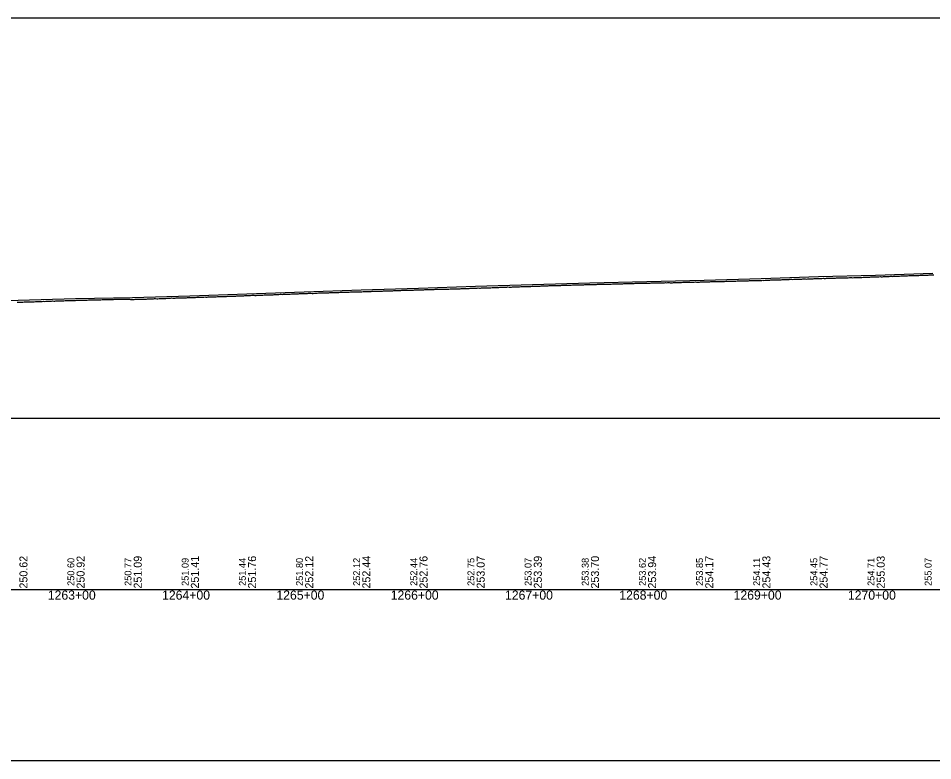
# Model space of a CAD drawing. Extents: x -3627 to 47473, y 2850 to 4350.
# Drawn here: x 13627 to 14427, y 2850 to 3500 of the extents above; entities that cross this region are included whole.
import ezdxf

# ---------------------------------------------------------------- set-up
doc = ezdxf.new("R2010")
doc.units = 0
for name, color, linetype in [('RD_DDB_Profile_EX', 7, 'Continuous'), ('RD_DDB_Profile_PR', 7, 'Continuous'), ('RD_DDB_StaTX', 7, 'Continuous'), ('RD_DDB_StripGrade', 7, 'Continuous'), ('RD_GPK_Profile_Cell', 7, 'Continuous'), ('RD_SHT_ShtClip', 7, 'Continuous')]:
    doc.layers.add(name, color=color, linetype=linetype)

msp = doc.modelspace()

# ---------------------------------------------------------------- linework, layer by layer
at = {"layer": 'RD_DDB_Profile_EX'}
for points in [[(14255.212154, 3269.888575), (14256.208332, 3270.01727), (14257.211431, 3270.0104), (14258.21036, 3270.0803), (14259.213447, 3270.05244), (14260.216534, 3270.00943), (14261.208566, 3270.016285), (14262.211652, 3270.17328), (14263.160721, 3270.16539), (14264.163914, 3270.21514), (14265.161646, 3270.215845), (14266.159104, 3270.228985), (14267.162291, 3270.285905), (14268.166428, 3270.364425), (14269.163874, 3270.370585), (14270.161626, 3270.364065), (14271.164806, 3270.28536), (14272.162253, 3270.37729), (14273.16639, 3270.355355), (14273.703458, 3270.44157), (14274.706852, 3270.505755), (14275.703982, 3270.55652), (14276.70738, 3270.563455), (14277.699517, 3270.563345), (14278.702916, 3270.577575), (14279.699196, 3270.57086), (14280.703436, 3270.620755), (14281.706835, 3270.727745), (14282.703953, 3270.821175), (14283.707357, 3270.813755), (14284.703635, 3270.857195), (14285.707876, 3270.89277), (14286.699165, 3270.906795), (14287.703407, 3270.89949), (14288.699674, 3270.90017), (14289.703086, 3270.957025), (14290.700179, 3270.979085), (14291.703596, 3271.071755), (14292.70068, 3271.072425), (14293.704103, 3271.09341), (14294.700363, 3271.143805), (14295.699628, 3271.17185), (14296.697062, 3271.17933), (14297.701308, 3271.193385), (14298.697549, 3271.27973), (14299.700982, 3271.322465), (14300.698032, 3271.387115), (14301.70147, 3271.44393), (14302.705716, 3271.49385), (14303.701955, 3271.472125), (14304.705394, 3271.38602), (14305.697475, 3271.479), (14306.700915, 3271.59298), (14307.69795, 3271.58608), (14308.701396, 3271.644155), (14309.697624, 3271.60842), (14310.701872, 3271.64448), (14311.698096, 3271.724225), (14312.702344, 3271.731015), (14313.698563, 3271.75207), (14314.697063, 3271.794465), (14315.694072, 3271.83121), (14316.697531, 3271.687895), (14317.694529, 3271.75214), (14318.697995, 3271.972565), (14319.694203, 3271.895545), (14320.698454, 3271.88183), (14321.681263, 3271.94854), (14322.685493, 3271.99161), (14323.687805, 3272.179645), (14324.679811, 3272.18641), (14325.683237, 3272.243185), (14326.680346, 3272.279745), (14327.402521, 3272.2526), (14328.26452, 3272.253065), (14329.402779, 3272.25963), (14330.399444, 3272.323345), (14331.403032, 3272.34652), (14332.266746, 3272.302615), (14333.398667, 3272.309695), (14334.267858, 3272.39619), (14335.398909, 3272.339935), (14336.268971, 3272.33985), (14337.397973, 3272.50367), (14338.401567, 3272.503515), (14339.398209, 3272.46055), (14340.397196, 3272.47998), (14341.267273, 3272.479955), (14342.397432, 3272.58011), (14343.268392, 3272.623445), (14344.397663, 3272.667075), (14345.269511, 3272.623625), (14346.397886, 3272.667295), (14347.27063, 3272.66725), (14348.393511, 3272.7), (14349.265598, 3272.786835), (14350.392566, 3272.843485), (14351.39687, 3272.886945), (14352.400481, 3272.8), (14353.397083, 3272.79352), (14354.400701, 3272.930485)], [(14354.400701, 3272.930485), (14355.261866, 3272.973945), (14356.265958, 3273.0239), (14357.262979, 3272.89353), (14358.396527, 3272.912985), (14359.393098, 3273.06788), (14360.396728, 3273.06777), (14361.265205, 3273.11174), (14362.395787, 3273.14361), (14363.265402, 3273.143525), (14364.391393, 3273.130735), (14365.266521, 3273.04357), (14366.391582, 3273.26812), (14367.26764, 3273.31169), (14368.391764, 3273.211395), (14369.26876, 3273.211265), (14370.38737, 3273.44364), (14371.263698, 3273.44363), (14372.395324, 3273.45), (14373.264811, 3273.53735), (14374.395501, 3273.5873), (14375.265924, 3273.587445), (14376.394548, 3273.58742), (14377.326954, 3273.55), (14378.324748, 3273.50631), (14379.321977, 3273.675035), (14380.325404, 3273.637475), (14381.321637, 3273.819095), (14382.325835, 3273.781425), (14383.330033, 3273.756205), (14384.326485, 3273.8), (14385.329704, 3273.843855), (14386.321498, 3273.806155), (14387.325698, 3274.0315), (14388.321166, 3273.97562), (14389.325364, 3273.98168), (14390.322556, 3274.131895), (14391.325046, 3274.08791), (14392.304382, 3274.03183), (14393.301534, 3274.17007), (14394.297714, 3274.28229), (14395.301194, 3274.25852), (14396.298322, 3274.26488), (14397.295427, 3274.332655), (14398.297996, 3274.25), (14399.2951, 3274.39428), (14400.299306, 3274.44427), (14401.295479, 3274.49435), (14402.291867, 3274.477655), (14403.296074, 3274.516415), (14404.292244, 3274.48897), (14405.288624, 3274.522745), (14406.298278, 3274.7016), (14407.295307, 3274.712875), (14408.298661, 3274.75), (14409.295039, 3274.7), (14410.292043, 3274.7345), (14411.295419, 3274.90866), (14412.292411, 3274.879625), (14413.288768, 3274.79497), (14414.292166, 3274.77988), (14415.289133, 3274.920275), (14416.292735, 3274.995025), (14417.288902, 3274.99022), (14418.285844, 3274.964445), (14419.290052, 3275.00965), (14420.286393, 3275.08572), (14421.289835, 3275.12619), (14422.286753, 3275.2172), (14423.283085, 3275.17691), (14424.28655, 3275.317655), (14425.283442, 3275.345455), (14426.280309, 3275.32767), (14427.283254, 3275.37313), (14428.28012, 3275.3912)], [(13955.965101, 3261.59005), (13956.969299, 3261.63008), (13957.965531, 3261.67036), (13958.968505, 3261.68018), (13959.966314, 3261.740155), (13960.968944, 3261.78032), (13961.966742, 3261.79022), (13962.969729, 3261.819615), (13963.965969, 3261.85), (13965.034611, 3261.85972), (13966.031974, 3261.95), (13967.034589, 3261.901745), (13968.02579, 3261.90178), (13969.03006, 3261.98069), (13970.025761, 3262), (13971.03003, 3262.009585), (13972.033728, 3262.05), (13973.029433, 3262.1), (13974.033702, 3262.140505), (13975.029408, 3262.18117), (13976.02753, 3262.2), (13977.024852, 3262.19349), (13978.027509, 3262.234115), (13979.031777, 3262.302885), (13980.027487, 3262.331315), (13981.030157, 3262.27199), (13982.027466, 3262.353625), (13983.025592, 3262.421975), (13984.021307, 3262.431475), (13985.025575, 3262.45), (13986.028258, 3262.5), (13987.023986, 3262.59081), (13988.028252, 3262.6316), (13989.019404, 3262.613225), (13990.023671, 3262.613185), (13991.026366, 3262.65401), (13992.022099, 3262.72264), (13993.027387, 3262.70443), (13994.023112, 3262.73675), (13995.02124, 3262.77718), (13996.018513, 3262.836715), (13997.021235, 3262.79579), (13998.025501, 3262.78668), (13999.02123, 3262.77826), (14000.023965, 3262.828305), (14001.021224, 3262.9788), (14002.019357, 3262.9462), (14003.015091, 3262.937775), (14004.019356, 3262.928805), (14005.022103, 3263.011055), (14006.01785, 3263.07065), (14007.022113, 3263.13821), (14008.013225, 3263.179425), (14009.01749, 3263.161675), (14010.013228, 3263.153695), (14011.016, 3263.18), (14012.020263, 3263.22372), (14013.016014, 3263.21527), (14014.015125, 3263.206325), (14014.697908, 3263.33064), (14015.696146, 3263.305315), (14016.699021, 3263.305365), (14017.69725, 3263.38167), (14018.700134, 3263.42317), (14019.867069, 3263.49077), (14020.701247, 3263.49071), (14021.698268, 3263.54929), (14022.70236, 3263.657565), (14023.70056, 3263.691615), (14024.704654, 3263.649895), (14025.695783, 3263.716615), (14026.699878, 3263.733145), (14027.696877, 3263.73376), (14028.700972, 3263.74197), (14029.696812, 3263.86709), (14030.700905, 3263.82586), (14031.699073, 3263.8346), (14032.702009, 3263.892805), (14033.700167, 3263.985135), (14034.703112, 3263.99327), (14035.700126, 3264.00167), (14036.697136, 3264.04416), (14037.701229, 3264.086095), (14038.699362, 3264.07868), (14039.702333, 3264.128715), (14040.700456, 3264.129285), (14041.860354, 3264.16344), (14042.694504, 3264.205465), (14043.697481, 3264.21338), (14044.695597, 3264.203135), (14045.699692, 3264.406145), (14046.696691, 3264.39159), (14047.700786, 3264.406955), (14048.696702, 3264.492345), (14049.700795, 3264.473), (14050.697805, 3264.4814), (14051.701898, 3264.508405), (14052.699981, 3264.59404), (14053.703002, 3264.589475), (14054.700015, 3264.639885), (14055.703045, 3264.74742)], [(14055.703045, 3264.74742), (14056.701119, 3264.718085), (14057.699174, 3264.7188), (14058.702222, 3264.73359), (14059.700268, 3264.81223), (14060.69731, 3264.83181), (14061.694316, 3264.84731), (14062.69737, 3264.897345), (14063.69541, 3264.92006), (14064.873141, 3265.006855), (14065.877438, 3265.01358), (14066.867591, 3265.04182), (14067.871888, 3265.085), (14068.867382, 3265.142845), (14069.87168, 3265.142765), (14070.868422, 3265.12911), (14071.871471, 3265.10039), (14072.875769, 3265.20032), (14073.870512, 3265.236715), (14074.874808, 3265.272535), (14075.865712, 3265.2796), (14076.87001, 3265.336545), (14077.866734, 3265.415075), (14078.730553, 3265.372025), (14079.865775, 3265.41685), (14080.868853, 3265.580725), (14081.863621, 3265.581385), (14082.867916, 3265.538155), (14083.863427, 3265.53886), (14084.863099, 3265.644955), (14085.858602, 3265.659185), (14086.862898, 3265.638685), (14087.858866, 3265.7689), (14088.861974, 3265.80946), (14089.866269, 3265.802625), (14090.86178, 3265.853175), (14091.866075, 3265.9098), (14092.862751, 3265.95357), (14093.86052, 3265.959675), (14094.8572, 3265.94677), (14095.860326, 3266.02682), (14096.856994, 3266.03414), (14097.860133, 3266.040735), (14098.856789, 3266.071785), (14099.860386, 3266.12806), (14100.855892, 3266.185385), (14101.860188, 3266.191755), (14102.851032, 3266.267645), (14103.855329, 3266.267595), (14105.122149, 3266.26673), (14106.119181, 3266.261265), (14107.122665, 3266.31184), (14108.113503, 3266.336405), (14109.117736, 3266.39904), (14110.113709, 3266.39967), (14111.117942, 3266.45589), (14112.114946, 3266.493895), (14113.117414, 3266.5438), (14114.114416, 3266.55676), (14115.110386, 3266.563415), (14116.114619, 3266.651135), (14117.110589, 3266.595735), (14118.114822, 3266.56376), (14119.111077, 3266.664105), (14120.114322, 3266.708125), (14121.111277, 3266.77043), (14122.114533, 3266.726345), (14123.111477, 3266.832465), (14124.109551, 3266.82038), (14125.105801, 3266.82067), (14126.110035, 3266.86474), (14127.106001, 3266.892025), (14128.110235, 3266.9303), (14129.106201, 3266.99844), (14130.110435, 3267.004085), (14131.106401, 3266.87736), (14132.109967, 3266.99887), (14133.106869, 3267.03827), (14134.110175, 3267.088265), (14135.107066, 3267.09457), (14136.110383, 3267.10011), (14137.107263, 3267.150735), (14138.110852, 3267.206045), (14139.106824, 3267.195855), (14140.098447, 3267.195745), (14141.089175, 3267.19574), (14142.088211, 3267.22828), (14143.094654, 3267.166895), (14144.093097, 3267.17191), (14145.088996, 3267.30569), (14146.088092, 3267.338075), (14147.092336, 3267.38796), (14148.090497, 3267.40996), (14149.094741, 3267.448425), (14150.092893, 3267.49771), (14151.09646, 3267.591695), (14152.094594, 3267.584995), (14153.098835, 3267.5908), (14154.096961, 3267.59002), (14155.093863, 3267.596625), (14156.093001, 3267.59583)], [(14156.093001, 3267.59583), (14157.096239, 3267.68981), (14158.094673, 3267.72047), (14159.097895, 3267.70212), (14160.097036, 3267.663125), (14161.100243, 3267.768975), (14162.099389, 3267.71854), (14163.102582, 3267.730795), (14164.101734, 3267.72984), (14165.098702, 3267.905815), (14166.096071, 3267.910415), (14167.100311, 3267.96027), (14168.098406, 3267.948125), (14169.102646, 3267.954535), (14170.100732, 3268.054015), (14171.104972, 3268.0171), (14172.108117, 3268.06053), (14173.106511, 3268.05327), (14174.103546, 3268.010335), (14175.101623, 3268.08984), (14176.105862, 3268.11966), (14177.103932, 3268.082315), (14178.10817, 3268.09577), (14179.106232, 3268.188335), (14180.109666, 3268.23814), (14181.108865, 3268.251295), (14181.668883, 3268.251255), (14182.671988, 3268.301265), (14183.669912, 3268.294815), (14184.673027, 3268.26035), (14185.670941, 3268.34534), (14186.668054, 3268.380955), (14187.671195, 3268.394585), (14188.66813, 3268.395195), (14189.672234, 3268.45197), (14190.670332, 3268.39444), (14191.667256, 3268.431305), (14192.671361, 3268.524325), (14193.668286, 3268.55237), (14194.671441, 3268.509045), (14195.668543, 3268.60171), (14196.666459, 3268.53633), (14197.669582, 3268.5295), (14198.673686, 3268.497355), (14199.671593, 3268.51865), (14200.668706, 3268.65204), (14201.672811, 3268.645105), (14202.669736, 3268.672855), (14203.672866, 3268.73215), (14204.664717, 3268.739055), (14205.668823, 3268.788965), (14206.671954, 3268.788975), (14207.66888, 3268.796355), (14208.672984, 3268.83956), (14209.670097, 3268.838915), (14210.667023, 3268.90602), (14211.671127, 3268.89916), (14212.674267, 3268.939505), (14213.671204, 3268.96359), (14214.670206, 3269.00594), (14215.667122, 3268.97691), (14216.670273, 3268.93357), (14217.674378, 3268.996775), (14218.665266, 3269.096785), (14219.668416, 3269.120195), (14220.672521, 3269.076735), (14221.669448, 3269.077545), (14222.672607, 3269.07756), (14223.210142, 3269.097275), (14224.208818, 3269.18349), (14225.204956, 3269.184225), (14226.209167, 3269.22095), (14227.20704, 3269.256785), (14228.210176, 3269.28343), (14229.214384, 3269.246665), (14230.205261, 3269.296675), (14231.208396, 3269.34002), (14232.206248, 3269.382655), (14233.210456, 3269.425815), (14234.207427, 3269.426735), (14235.205286, 3269.432695), (14236.209494, 3269.44608), (14237.212617, 3269.43935), (14238.210459, 3269.468305), (14239.207711, 3269.53253), (14240.210833, 3269.6258), (14241.208672, 3269.618225), (14242.212878, 3269.63176), (14243.209048, 3269.675725), (14244.207717, 3269.67509), (14245.211924, 3269.681805), (14246.209763, 3269.71735), (14247.212862, 3269.724255), (14248.210136, 3269.74539), (14249.207973, 3269.78106), (14250.211071, 3269.824185), (14251.215276, 3269.860275), (14252.206182, 3269.903395), (14253.20928, 3269.960315), (14254.213484, 3269.88947), (14255.212154, 3269.888575)], [(13756.488564, 3254.767665), (13757.48749, 3254.84849), (13758.490472, 3254.972235), (13759.49464, 3255.022205), (13760.484665, 3255.03145), (13761.488833, 3255.11286), (13762.487777, 3255.08127), (13763.490741, 3255.034265), (13764.494909, 3255.093595), (13765.486389, 3255.17172), (13766.490559, 3255.190565), (13767.488064, 3255.2215), (13768.49101, 3255.20473), (13769.495179, 3255.204625), (13770.486679, 3255.32131), (13771.490849, 3255.30213), (13772.493787, 3255.342395), (13773.49128, 3255.39202), (13774.495448, 3255.382285), (13775.48697, 3255.4112), (13776.49114, 3255.42087), (13777.49406, 3255.46105), (13778.493064, 3255.61073), (13779.494454, 3255.61069), (13780.48726, 3255.542605), (13781.49143, 3255.612135), (13782.494333, 3255.6605), (13783.493354, 3255.780095), (13784.496244, 3255.690305), (13785.494227, 3255.721015), (13786.529588, 3255.78047), (13787.527622, 3255.801265), (13788.525637, 3255.8313), (13789.528522, 3255.83111), (13790.526531, 3255.992395), (13791.523262, 3255.972085), (13792.525932, 3255.98187), (13793.522667, 3256.04186), (13794.512479, 3256.022965), (13795.510494, 3256.023445), (13796.514649, 3256.0021), (13797.517941, 3256.083865), (13798.513263, 3256.146745), (13799.517417, 3256.14663), (13800.515395, 3256.22531), (13801.512142, 3256.303545), (13802.514884, 3256.335005), (13803.512844, 3256.34466), (13804.509587, 3256.4174), (13805.512347, 3256.376625), (13806.510288, 3256.48178), (13807.507028, 3256.48187), (13808.516539, 3256.39599), (13809.513092, 3256.52862), (13810.509833, 3256.641125), (13811.513988, 3256.632225), (13812.511881, 3256.67353), (13813.507277, 3256.72372), (13814.511433, 3256.74738), (13815.509307, 3256.706465), (13816.507161, 3256.767285), (13817.508872, 3256.85), (13818.506727, 3256.85859), (13819.50997, 3256.9), (13820.511735, 3257.02462), (13821.509567, 3256.991605), (13822.50738, 3257.02501), (13823.510448, 3257.116575), (13824.506991, 3257.13345), (13825.504784, 3257.15), (13826.507869, 3257.191765), (13827.505654, 3257.18366), (13828.502183, 3257.23382), (13829.505284, 3257.291885), (13830.508523, 3257.384055), (13831.506265, 3257.442095), (13832.508185, 3257.492085), (13833.369526, 3257.4683), (13834.368494, 3257.417945), (13835.371417, 3257.33398), (13836.369384, 3257.517545), (13837.373576, 3257.617505), (13838.372566, 3257.584305), (13839.374434, 3257.58422), (13840.373422, 3257.69169), (13841.371004, 3257.708245), (13842.368984, 3257.758345), (13843.371855, 3257.841655), (13844.370868, 3257.88314), (13845.37401, 3257.941545), (13846.373038, 3257.908545), (13847.375878, 3257.99146), (13848.320071, 3258.02408), (13849.322927, 3257.974095), (13850.321424, 3257.973835), (13851.324359, 3258.082505), (13852.316816, 3258.164965), (13853.319654, 3258.241245), (13854.323778, 3258.264945), (13855.321101, 3258.264535), (13856.323924, 3258.39114)], [(13856.323924, 3258.39114), (13857.322452, 3258.346325), (13858.325355, 3258.31411), (13859.322571, 3258.431915), (13860.326693, 3258.481895), (13861.325246, 3258.5), (13862.328123, 3258.53167), (13863.325335, 3258.485375), (13864.323475, 3258.48997), (13865.320796, 3258.542405), (13866.32356, 3258.740735), (13867.32214, 3258.762605), (13868.326264, 3258.771925), (13869.322198, 3258.781115), (13870.32632, 3258.783825), (13871.324926, 3258.79278), (13872.327748, 3258.852175), (13873.324955, 3258.922955), (13874.329077, 3258.99036), (13875.321786, 3259.00965), (13876.323178, 3258.982365), (13877.321811, 3259.02204), (13878.325935, 3259.10122), (13879.323148, 3259.07054), (13880.325931, 3259.170455), (13881.324589, 3259.23014), (13882.328712, 3259.33012), (13883.324558, 3259.35), (13884.32868, 3259.170065), (13885.327362, 3259.160115), (13886.330002, 3259.3), (13886.863725, 3259.33018), (13887.863355, 3259.32901), (13888.865904, 3259.408795), (13889.868971, 3259.55), (13890.866558, 3259.5), (13891.864491, 3259.539835), (13892.868735, 3259.589825), (13893.865146, 3259.6), (13894.864785, 3259.639785), (13895.867322, 3259.639795), (13896.863735, 3259.669505), (13897.867979, 3259.708415), (13898.865909, 3259.70785), (13899.870153, 3259.7795), (13900.866568, 3259.848965), (13901.864496, 3259.84865), (13902.86874, 3259.898595), (13903.86634, 3259.98978), (13904.85322, 3259.91815), (13905.852741, 3259.90719), (13906.847531, 3259.970505), (13907.851759, 3259.86921), (13908.851284, 3260.08794), (13909.847762, 3260.1397), (13910.850297, 3260.15), (13911.854525, 3260.15), (13912.854055, 3260.15), (13913.848836, 3260.139675), (13914.853064, 3260.189665), (13915.852598, 3260.26875), (13916.848601, 3260.268985), (13917.851603, 3260.418895), (13918.85583, 3260.368865), (13919.847143, 3260.37926), (13920.851372, 3260.37924), (13921.854369, 3260.41877), (13922.852189, 3260.43717), (13923.849915, 3260.516705), (13924.852908, 3260.6), (13925.855421, 3260.5), (13926.848457, 3260.58734), (13927.852686, 3260.62682), (13928.976973, 3260.687205), (13929.974891, 3260.72716), (13930.979086, 3260.8), (13931.975342, 3260.78966), (13932.973332, 3260.789565), (13933.971236, 3260.829245), (13934.975433, 3260.868835), (13935.971676, 3260.91907), (13936.974593, 3260.95), (13937.972479, 3260.96028), (13938.975042, 3261.05), (13939.972917, 3261.04895), (13940.975847, 3260.998805), (13941.972098, 3261.02888), (13942.976293, 3261.128805), (13943.972898, 3261.129105), (13944.970541, 3261.18885), (13945.968401, 3261.199345), (13946.972599, 3261.3), (13947.96759, 3261.249595), (13948.971786, 3261.27936), (13949.969628, 3261.28982), (13950.97223, 3261.349885), (13951.968828, 3261.360085), (13952.973024, 3261.46004), (13953.969269, 3261.45), (13954.973466, 3261.45), (13955.965101, 3261.59005)], [(13626.41194, 3251.579205), (13627.409515, 3251.48767), (13628.416024, 3251.535825), (13629.413612, 3251.58475), (13630.416385, 3251.54241), (13631.413961, 3251.559125), (13632.412941, 3251.6859), (13633.416464, 3251.67405), (13634.415697, 3251.7013), (13635.279637, 3251.66852), (13636.283911, 3251.718395), (13637.27958, 3251.80199), (13638.283854, 3251.8519), (13639.279522, 3251.88506), (13640.277589, 3251.841175), (13641.281863, 3251.847495), (13642.277536, 3252.01755), (13643.281809, 3251.991735), (13644.277482, 3252.014), (13645.281755, 3252.0462), (13646.279823, 3252.12836), (13647.277351, 3252.113905), (13648.279773, 3252.17096), (13649.276104, 3252.203575), (13650.278536, 3252.185765), (13651.278447, 3252.19216), (13652.274124, 3252.192925), (13653.278397, 3252.267845), (13654.274075, 3252.378715), (13655.278348, 3252.38283), (13656.276418, 3252.403595), (13657.2721, 3252.489365)], [(13657.2721, 3252.489365), (13658.276373, 3252.45419), (13659.272055, 3252.42317), (13660.276327, 3252.536525), (13661.278783, 3252.53657), (13662.271902, 3252.58942), (13663.274357, 3252.6), (13664.278628, 3252.678835), (13665.274315, 3252.678985), (13666.278587, 3252.718445), (13667.269882, 3252.76847), (13668.274155, 3252.7974), (13669.275448, 3252.77629), (13670.272943, 3252.80811), (13671.275418, 3252.84768), (13672.271118, 3252.83767), (13673.27098, 3252.916265), (13674.273456, 3252.926785), (13675.270942, 3253.018795), (13676.27343, 3253.029215), (13677.270905, 3253.018995), (13678.268983, 3253.07921), (13679.273253, 3253.09797), (13680.26895, 3253.076035), (13681.27322, 3253.07591), (13682.268916, 3253.160265), (13683.268768, 3253.179315), (13684.271265, 3253.146645), (13685.062333, 3253.22669), (13685.639517, 3253.22662), (13686.642094, 3253.308905), (13687.608298, 3253.31935), (13688.606452, 3253.38984), (13689.609069, 3253.38985), (13690.607213, 3253.399535), (13691.609841, 3253.4794), (13692.607975, 3253.46978), (13693.610612, 3253.419735), (13694.608737, 3253.430455), (13695.611384, 3253.510405), (13696.609498, 3253.54114), (13697.60685, 3253.54046), (13698.604957, 3253.5708), (13699.607613, 3253.620855), (13700.60571, 3253.740995), (13701.608376, 3253.741035), (13702.604992, 3253.68173), (13703.609138, 3253.73166), (13704.605755, 3253.751565), (13705.609901, 3253.791815), (13706.605243, 3253.851805), (13707.609388, 3253.892105), (13708.606014, 3253.89256), (13709.610159, 3253.904165), (13710.606786, 3253.9359), (13711.604833, 3254.002755), (13712.607557, 3254.043345), (13713.605594, 3254.07493), (13714.608328, 3254.0656), (13715.600986, 3254.0749), (13716.603719, 3254.028035), (13717.600335, 3254.06971), (13718.604481, 3254.11615), (13719.601098, 3254.157585), (13720.605244, 3254.148235), (13721.601861, 3254.012355), (13722.606007, 3253.97139), (13723.602623, 3254.095335), (13724.60677, 3254.03615), (13725.603386, 3253.90477), (13726.606333, 3253.904645), (13727.602959, 3253.85), (13728.607104, 3253.913975), (13729.60373, 3253.996415), (13730.607876, 3254.046355), (13731.604502, 3254.08794), (13732.601128, 3254.12089), (13733.599824, 3254.161295), (13734.596441, 3254.188435), (13735.600587, 3254.14717), (13736.597203, 3254.19762), (13737.60135, 3254.2063), (13738.594363, 3254.2066), (13739.486908, 3254.212255), (13740.484708, 3254.295435), (13741.48223, 3254.388545), (13742.485269, 3254.329565), (13743.489437, 3254.34711), (13744.487174, 3254.39654), (13745.484995, 3254.5146), (13746.482747, 3254.60527), (13747.486916, 3254.60522), (13748.489703, 3254.510495), (13749.48744, 3254.50954), (13750.485282, 3254.669125), (13751.488295, 3254.68692), (13752.487203, 3254.731815), (13753.490202, 3254.727055), (13754.487706, 3254.70818), (13755.485569, 3254.80439), (13756.488564, 3254.767665)]]:
    msp.add_lwpolyline(points, dxfattribs=at)
at = {"layer": 'RD_DDB_Profile_PR'}
msp.add_lwpolyline([(13577.33, 3251.615), (13627.33, 3253.095), (13677.33, 3254.6225), (13727.33, 3255.465), (13777.33, 3257.0545), (13827.33, 3258.785), (13877.33, 3260.6225), (13927.33, 3262.2065), (13977.33, 3263.806), (14027.33, 3265.3335), (14077.33, 3266.973), (14127.33, 3268.5005), (14177.33, 3269.6855), (14227.33, 3270.86), (14277.33, 3272.1635), (14327.33, 3273.8555), (14377.33, 3275.15), (14427.33, 3276.974)], dxfattribs=at)
at = {"layer": 'RD_GPK_Profile_Cell'}
msp.add_line((1000, 3000), (46705.077602, 3000), dxfattribs=at)
at = {"layer": 'RD_SHT_ShtClip'}
for points in [[(14500.165, 3000), (14500.165, 3500), (14500.165, 3500), (13000.33, 3500), (13000.33, 3000)], [(12980.33, 3150), (14520, 3150), (14520, 2850), (12980.33, 2850)]]:
    msp.add_lwpolyline(points, close=True, dxfattribs=at)

# ---------------------------------------------------------------- texts
at = {"layer": 'RD_DDB_StaTX'}
for s, p in [('1263+00', (13653.125471, 2991)), ('1264+00', (13753.125471, 2991)), ('1265+00', (13853.125471, 2991)), ('1266+00', (13953.125471, 2991)), ('1267+00', (14053.125471, 2991)), ('1268+00', (14153.125471, 2991)), ('1269+00', (14253.125471, 2991)), ('1270+00', (14353.125471, 2991))]:
    msp.add_text(s, height=8, dxfattribs=at).set_placement(p)
at = {"layer": 'RD_DDB_StripGrade'}
for s, height, p in [('250.62', 7, (13635.33, 3000.75)), ('250.60', 6, (13676.33, 3003.073688)), ('250.92', 7, (13685.33, 3000.75)), ('250.77', 6, (13726.33, 3003.073688)), ('251.09', 7, (13735.33, 3000.75)), ('251.09', 6, (13776.33, 3003.073688)), ('251.41', 7, (13785.33, 3000.75)), ('251.44', 6, (13826.33, 3003.073688)), ('251.76', 7, (13835.33, 3000.75)), ('251.80', 6, (13876.33, 3003.073688)), ('252.12', 7, (13885.33, 3000.75)), ('252.12', 6, (13926.33, 3003.073688)), ('252.44', 7, (13935.33, 3000.75)), ('252.44', 6, (13976.33, 3003.073688)), ('252.76', 7, (13985.33, 3000.75)), ('252.75', 6, (14026.33, 3003.073688)), ('253.07', 7, (14035.33, 3000.75)), ('253.07', 6, (14076.33, 3003.073688)), ('253.39', 7, (14085.33, 3000.75)), ('253.38', 6, (14126.33, 3003.073688)), ('253.70', 7, (14135.33, 3000.75)), ('253.62', 6, (14176.33, 3003.073688)), ('253.94', 7, (14185.33, 3000.75)), ('253.85', 6, (14226.33, 3003.073688)), ('254.17', 7, (14235.33, 3000.75)), ('254.11', 6, (14276.33, 3003.073688)), ('254.43', 7, (14285.33, 3000.75)), ('254.45', 6, (14326.33, 3003.073688)), ('254.77', 7, (14335.33, 3000.75)), ('254.71', 6, (14376.33, 3003.073688)), ('255.03', 7, (14385.33, 3000.75)), ('255.07', 6, (14426.33, 3003.073688))]:
    msp.add_text(s, height=height, rotation=90, dxfattribs=at).set_placement(p)

doc.saveas('drawing.dxf')
